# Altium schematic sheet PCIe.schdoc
size 297 x 209 mm; Symbol: Drawing-Symbol_A4; Company: 嘉立创EDA; Version: V1.0; Page Size: A4; @Project Name: 远程开机卡; @Update Date: 2026-06-24; @Create Date: 2026-06-24; Device: Drawing-Symbol_A4; @Board Name: ESP32P4_PCIE_FULL; @Page Name: P5; @Create Time: 17:14:13; @Page Count: 8; @Page No: 0; @Schematic Name: SCH_3; @Update Time: 17:14:13; @Assembly Variant: Basic; Border: 1; Title Block Position: 3; Size: A4; Width: 1170; Height: 825; Region Start: 1; X Region Count: 6; Y Region Count: 4; Blade Width: 10
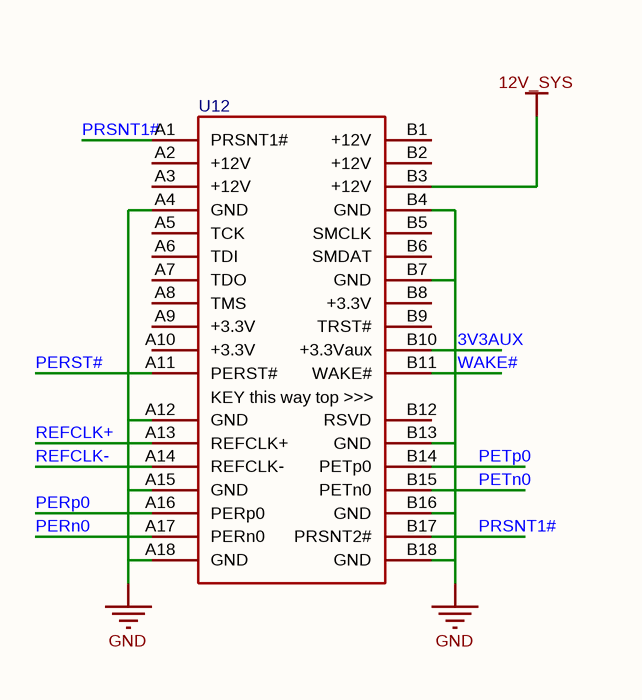
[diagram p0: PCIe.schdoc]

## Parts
U12  (no value)  [PCIe*1 key]

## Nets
12V_SYS: U12.B3(+12V)
GND: U12.A4(GND) U12.A12(GND) U12.A15(GND) U12.A18(GND) U12.B4(GND) U12.B7(GND) U12.B13(GND) U12.B16(GND) U12.B18(GND)
3V3AUX: U12.B10(+3.3Vaux)
PERn0: U12.A17(PERn0)
PERp0: U12.A16(PERp0)
PERST#: U12.A11(PERST#)
PETn0: U12.B15(PETn0)
PETp0: U12.B14(PETp0)
PRSNT1#: U12.A1(PRSNT1#) U12.B17(PRSNT2#)
REFCLK+: U12.A13(REFCLK+)
REFCLK-: U12.A14(REFCLK-)
WAKE#: U12.B11(WAKE#)

Not connected (* = marked no-connect by the designer): U12 A2(+12V) A3(+12V) A5(TCK) A6(TDI) A7(TDO) A8(TMS) A9(+3.3V) A10(+3.3V) B1(+12V) B2(+12V) B5(SMCLK) B6(SMDAT) B8(+3.3V) B9(TRST#) B12(RSVD)

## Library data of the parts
U12 = PCIe*1: Check: false; Add into BOM: no; ConvertToPcb: yes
